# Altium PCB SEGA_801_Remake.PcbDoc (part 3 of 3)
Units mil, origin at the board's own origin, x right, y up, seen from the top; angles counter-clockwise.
Board outline 5905.51 x 7590.41 mil, 2 copper layers (Top Layer, Bottom Layer), stack 61.811 mil thick; 192 components, 203 nets, 858 pads, 614 vias.
Unrouted connection lines stored in the file: 107.
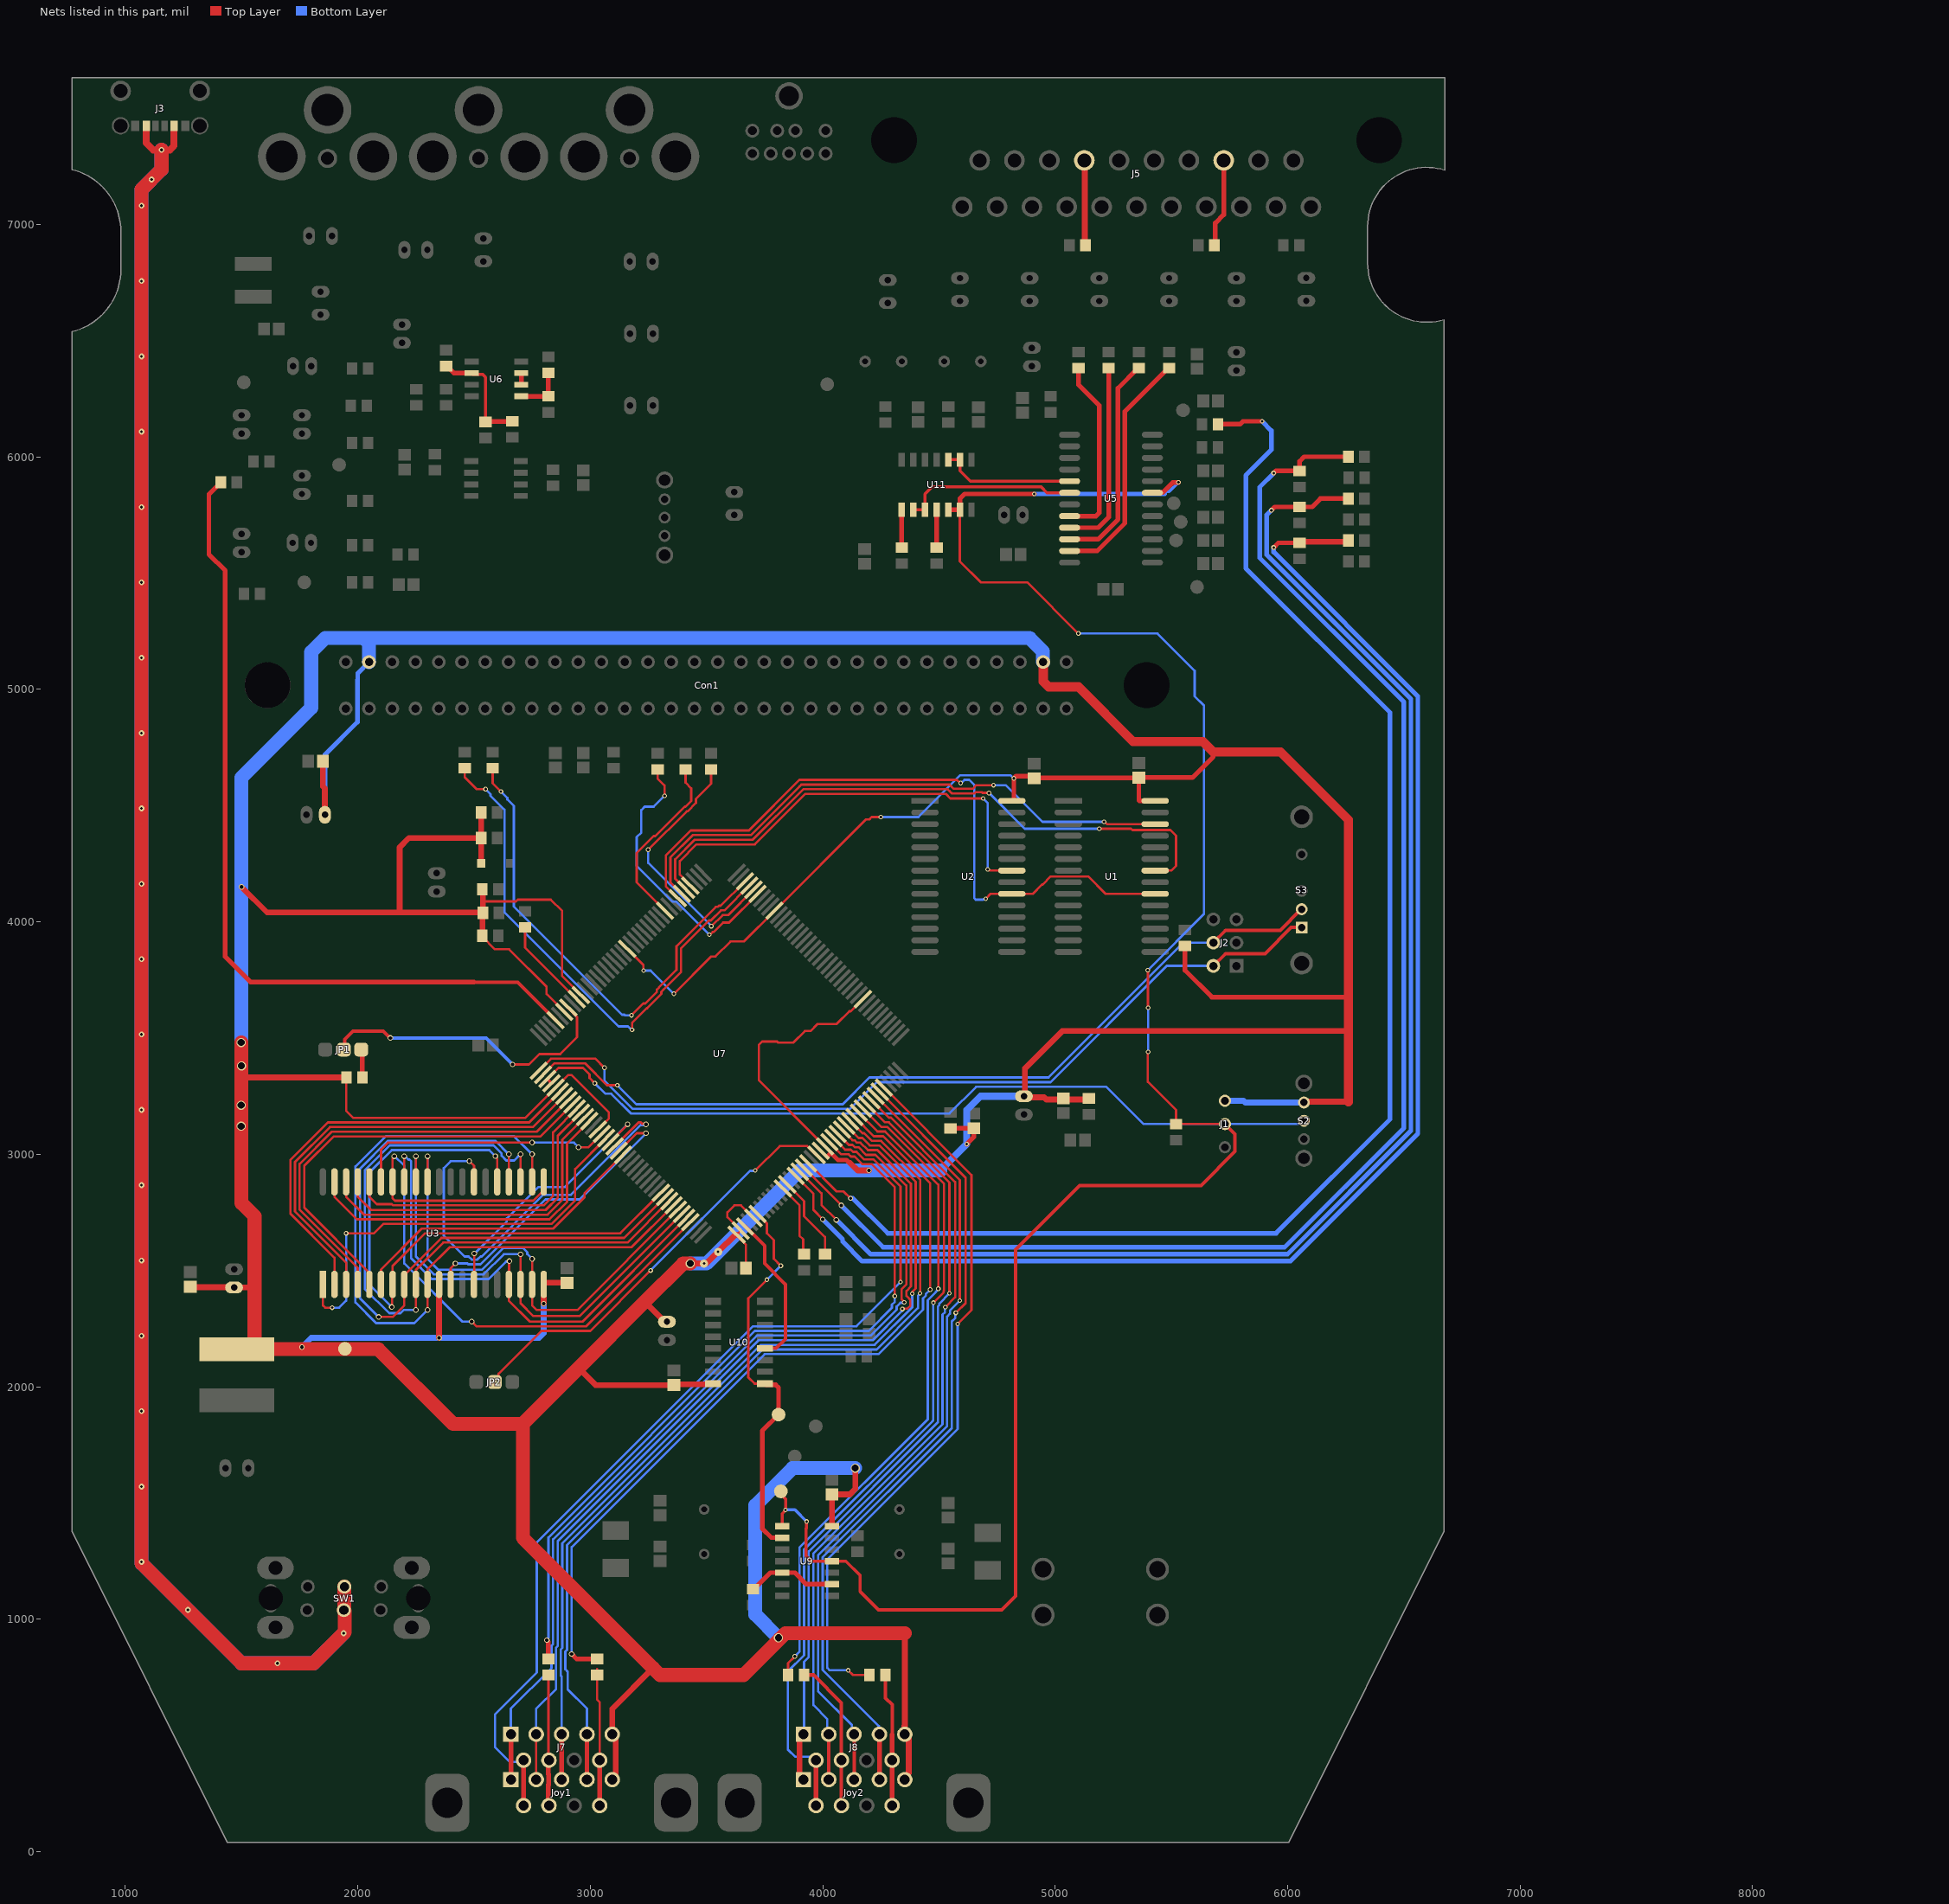
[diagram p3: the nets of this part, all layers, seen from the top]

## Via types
v1: diameter 25, hole 12, Top Layer to Bottom Layer, tented both sides, 269 vias
v2: diameter 19.68, hole 11.81, Top Layer to Bottom Layer, tented both sides, 183 vias
v3: diameter 31.5, hole 11.81, Top Layer to Bottom Layer, tented both sides, 82 vias
v4: diameter 23.62, hole 15.75, Top Layer to Bottom Layer, tented both sides, 36 vias
v5: diameter 35.43, hole 11.81, Top Layer to Bottom Layer, tented both sides, 35 vias
v6: diameter 39, hole 30, Top Layer to Bottom Layer, tented both sides, 7 vias
v7: diameter 19.68, hole 11.81, Top Layer to Bottom Layer, 2 vias

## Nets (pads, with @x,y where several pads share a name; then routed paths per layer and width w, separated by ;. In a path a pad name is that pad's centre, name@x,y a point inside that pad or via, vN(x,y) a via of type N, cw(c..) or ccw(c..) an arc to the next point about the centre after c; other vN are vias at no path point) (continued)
NetJ1_2: J1.2 R53.1 S2.2 TP4.1 U5.7 U7.3 U7.4 U9.1 U9.11 U11.5 U11.6 | length 12697.9
  Top Layer w10: U7.3@2815.27,3323.15 2815.67,3323.15 2863.53,3371.01 2969.25,3371.01 2997.41,3342.86 2997.41,3327.75 v2(3020,3305.16) ; U11.6@4590,5772.72 4590,5550 4680,5460 4880,5460 v2(5100,5240) ; v2(5398.29,3791.71) 5399.15,3790.85 5399.15,3630.85 v2(5400,3630) ; v2(5400,3440) 5398.29,3438.29 5398.29,3311.71 5520,3190 R53.1@5520,3128.9 5521.1,3130 J1.2@5730,3130
  Top Layer w13: U7.3@2815.27,3323.15 U7.4@2833.37,3305.05 ; TP4.1@3820,1550 3820,1537.54 3840,1517.54 v2(3840,1470) 3840,1468.19 3825.43,1453.62 U9.1@3825.43,1400 ; v2(3930.79,1420) 3929.51,1418.72 3929.51,1390.97 3927.44,1388.9 3927.44,1272.56 3950,1250 U9.11@4040,1250 4100,1250 4160,1190 4160,1120 4240,1040
  Top Layer w15: 4240,1040 4770,1040 4830,1100 4830,2589.8 5105.41,2865.22 5627.07,2865.22 5773.74,3011.88 5773.74,3086.26 J1.2@5730,3130
  Top Layer w20: U11.5@4540,5772.72 U11.6@4590,5772.72 4590,5820 4610,5840 v2(4910,5840) ; U5.7@5418.15,5845 5419.22,5846.07 5462.28,5846.07 5506.21,5890 v2(5530,5890)
  Bottom Layer w10: v2(3020,3305.16) 3065.16,3260 3090,3260 3174.79,3175.21 3181.64,3175.21 3181.69,3175.16 4545.16,3175.16 4659.96,3289.96 5220.04,3289.96 5380,3130 J1.2@5730,3130 6046.43,3130 6060.21,3143.78 S2.2@6070,3143.78 ; v2(5100,5240) 5440,5240 5600,5080 5600,4970 5640,4930 5640,4033.42 v2(5398.29,3791.71) ; v2(5400,3440) v2(5400,3630)
  Bottom Layer w13: v2(3840,1470) 3880.79,1470 v2(3930.79,1420) ; 5470,5840 5480,5850 5490,5850 v2(5530,5890)
  Bottom Layer w20: v2(4910,5840) 5470,5840
NetJ2_2: J2.2 S3.1 U7.1 | length 3747
  Top Layer w10: U7.1@2779.07,3359.35 2830.73,3411.01 3022.32,3411.01 v2(3061.11,3372.22)
  Top Layer w15: J2.2@5680,3810 5732.97,3862.97 5902.97,3862.97 6015.04,3975.04 S3.1@6060,3975.04
  Bottom Layer w10: v2(3061.11,3372.22) 3061.11,3317.17 3183.13,3195.16 4117.5,3195.16 4232.31,3309.96 4979.96,3309.96 5480,3810 J2.2@5680,3810
NetJ2_4: J2.4 S3.2 U7.2 | length 3703.6
  Top Layer w10: U7.2@2797.17,3341.25 2846.93,3391.01 2977.54,3391.01 3071.84,3296.71 v2(3116.71,3296.71)
  Top Layer w15: J2.4@5680,3910 5732.97,3962.97 5967.62,3962.97 6058.42,4053.78 S3.2@6060,4053.78
  Bottom Layer w10: v2(3116.71,3296.71) 3198.26,3215.16 4086.38,3215.16 4201.18,3329.96 4971.68,3329.96 5551.72,3910 J2.4@5680,3910
NetJ3_A9: J3.A9 J3.B9 SW1.3 SW1.4 | length 14937.1
  Top Layer w30: J3.A9@1090.16,7423.66 1090.16,7349.84 1120,7320 v7(1156.13,7320) 1192.27,7320 1209.84,7337.57 J3.B9@1209.84,7421.02
  Top Layer w60: v7(1156.13,7320) 1156.13,7235.98 1070,7149.84 1070,1240 1500,810 1810,810 1944.08,944.08 1944.08,1035.23 SW1.3@1940.25,1039.06 1942.46,1041.27 SW1.4@1942.46,1140
  Bottom Layer w60: v7(1156.13,7320) 1156.13,7236.13 1070,7150 1070,1240 1500,810 1810,810 v1@1940.73,940.73
  other v1: 1655,810 1939.72,939.72 1270,1040 1070,1246.48 1070,1570.57 1070,1894.65 1070,2218.73 1070,2542.82 1070,2866.9 1070,3190.99 1070,3515.07 1070,3839.16 1070,4163.24 1070,4487.32 1070,4811.41 1070,5135.49 1070,5459.58 1070,5783.66 1070,6107.75 1070,6431.83 1070,6755.92 1070,7080 1113.07,7193.07 1156.13,7320
NetJ5_8: J5.8 R72.2 | length 366.9
  Top Layer w25: J5.8@5125,7274.8 5127.5,7272.3 5127.5,6912.5 R72.2@5130,6910
NetJ5_16: J5.16 R71.2 | length 379.8
  Top Layer w20: R71.2@5688.9,6910 5688.9,7005.18 5725,7041.29 J5.16@5725,7274.8
NetJ7_1: J7.1 Joy1.1 U7.65 | length 3930.9
  Top Layer w10: U7.65@4064.31,3087.82 4112.37,3039.76 4128.53,3039.76 4138.28,3030 4153.81,3030 4186.31,2997.5 4227.04,2997.5 4359.69,2864.86 4359.69,2439.71 4340,2420.02 4340,2376.09 4350.38,2365.71 v2(4350.38,2363.09)
  Top Layer w20: Joy1.1@2658.78,330 J7.1@2658.78,504.92
  Bottom Layer w10: J7.1@2658.78,504.92 2658.78,614.96 2833.19,789.37 2833.19,886.28 2840,893.09 2840,1343.14 3716.86,2220 4206.57,2220 4317.87,2331.3 4317.87,2344.7 4334.4,2361.23 4348.53,2361.23 v2(4350.38,2363.09)
NetJ7_2: J7.2 Joy1.2 U7.66 | length 3917.5
  Top Layer w10: Joy1.2@2767.83,330 J7.2@2767.83,504.92 ; U7.66@4082.41,3105.93 4128.57,3059.76 4136.81,3059.76 4146.57,3050 4162.09,3050 4194.59,3017.5 4235.32,3017.5 4379.69,2873.14 4379.69,2431.43 4360,2411.74 4360,2389.97 4376.98,2373 4376.98,2348.43 4364.81,2336.26 4344.56,2336.26 v2(4342.71,2334.41)
  Bottom Layer w10: J7.2@2767.83,504.92 2767.83,614.96 2853.19,700.32 2853.19,877.67 2860,884.48 2860,1334.85 3725.15,2200 4215.15,2200 4340.86,2325.71 4340.86,2332.56 v2(4342.71,2334.41)
NetJ7_3: J7.3 Joy1.3 U7.67 | length 3872
  Top Layer w10: U7.67@4100.51,3124.03 4100.82,3124.03 4154.85,3070 4170.37,3070 4202.87,3037.5 4243.61,3037.5 4399.69,2881.42 4399.69,2423.14 4386.7,2410.15 4386.7,2402.12 v2(4384.84,2400.26)
  Top Layer w20: Joy1.3@2876.89,330 J7.3@2876.89,504.92
  Bottom Layer w10: J7.3@2876.89,504.92 2876.89,753.38 2873.19,757.08 2873.19,869.39 2880,876.2 2880,1326.57 3733.43,2180 4223.43,2180 4384.84,2341.41 v2(4384.84,2400.26)
NetJ7_4: J7.4 Joy1.4 U7.68 | length 3923.1
  Top Layer w10: U7.68@4118.61,3142.13 4170.74,3090 4178.66,3090 4211.16,3057.5 4251.89,3057.5 4419.69,2889.71 4419.69,2403.1 v2(4418.29,2401.71)
  Top Layer w20: Joy1.4@2985.94,330 J7.4@2985.94,504.92
  Bottom Layer w10: J7.4@2985.94,504.92 2985.94,614.96 2903.19,697.72 2903.19,774.41 2893.19,784.41 2893.19,861.11 2900,867.92 2900,1318.28 3741.72,2160 4231.72,2160 4409.69,2337.97 4409.69,2390.48 4418.29,2399.09 v2(4418.29,2401.71)
NetJ7_6: J7.6 Joy1.6 U7.64 | length 4097.7
  Top Layer w10: U7.64@4046.2,3069.72 4096.17,3019.76 4120.24,3019.76 4130,3010 4145.52,3010 4178.02,2977.5 4218.76,2977.5 4334.84,2861.41 v2(4334.84,2450)
  Top Layer w20: Joy1.6@2713.31,218.19 J7.6@2713.31,393.11
  Bottom Layer w10: J7.6@2713.31,393.11 2705.75,385.55 2654.45,385.55 2590,450 2590,590 2770,770 2770,1330 3700,2260 4144.84,2260 v2(4334.84,2450)
NetJ7_7: J7.7 Joy1.7 R78.1 | length 565.6
  Top Layer w10: R78.1@2820.25,759.75 2820.25,395.72 J7.7@2822.61,393.36
  Top Layer w20: Joy1.7@2822.36,198.11 2820,200.47 2820,286.75 2821.1,287.86 2821.1,331.99 2820,333.09 2820,390.75 J7.7@2822.61,393.36
NetJ7_9: J7.9 Joy1.9 R77.1 | length 565
  Top Layer w10: 3030,785.24 R77.1@3030,760 3030,653.67 3040.47,643.2 J7.9@3040.47,399.53
  Top Layer w20: Joy1.9@3040.47,218.19 J7.9@3040.47,393.11
NetJ8_1: J8.1 Joy2.1 U7.72 | length 3334.9
  Top Layer w10: U7.72@4191.02,3214.54 4268.06,3137.5 4285.03,3137.5 4545.16,2877.37 v2(4545.16,2401.71)
  Top Layer w25: J8.1@3915.47,504.92 3900,489.45 3900,326.81 Joy2.1@3916.89,309.92
  Bottom Layer w10: J8.1@3916.89,504.92 3920,508.03 3920,816.58 3940,836.58 3940,1291.24 4495.29,1846.53 4495.29,2345.02 4501.4,2351.13 4501.4,2357.95 v2(4545.16,2401.71)
NetJ8_2: J8.2 Joy2.2 U7.73 | length 3337.4
  Top Layer w10: U7.73@4209.12,3232.64 4284.26,3157.5 4293.31,3157.5 4570,2880.81 4570,2384.97 v2(4527.51,2342.48)
  Top Layer w15: Joy2.2@4025.94,330 J8.2@4025.95,504.92
  Bottom Layer w10: J8.2@4025.95,504.92 4020,510.87 4020,570 3960,630 3960,1282.95 4515.29,1838.24 4515.29,2310.14 4525.65,2320.51 4525.65,2340.62 v2(4527.51,2342.48)
NetJ8_3: J8.3 Joy2.3 U7.74 | length 3388.7
  Top Layer w10: U7.74@4227.22,3250.74 4300.46,3177.5 4301.6,3177.5 4590,2889.1 v2(4590,2370)
  Top Layer w15: Joy2.3@4135,330 J8.3@4135,504.92
  Bottom Layer w10: J8.3@4135,504.92 4125.91,514.01 4125.91,544.09 3980,690 3980,1274.67 4535.29,1829.96 4535.29,2301.86 4547.59,2314.16 4547.59,2327.43 4547.59,2327.86 4589.74,2370 v2(4590,2370)
NetJ8_4: J8.4 Joy2.4 U7.75 | length 3447.8
  Top Layer w10: U7.75@4245.32,3268.84 4614.84,2899.33 4614.84,2359.71 4572.7,2317.57 v2(4572.43,2317.57)
  Top Layer w20: Joy2.4@4244.06,330 J8.4@4244.06,504.92
  Bottom Layer w10: J8.4@4244.06,504.92 4241.79,507.18 4241.79,539.92 4000,781.72 4000,1266.39 4555.29,1821.68 4555.29,2280.16 4570.58,2295.45 4570.58,2315.71 v2(4572.43,2317.57)
NetJ8_6: J8.6 Joy2.6 U7.71 | length 3489.6
  Top Layer w10: U7.71@4172.92,3196.44 4251.85,3117.5 4276.75,3117.5 4522.04,2872.2 4522.04,2413.73 4520.32,2412 4520.32,2405.18 v2(4476.56,2361.42)
  Top Layer w20: Joy2.6@3971.42,218.19 J8.6@3971.42,393.11
  Bottom Layer w10: J8.6@3954.18,407.82 3950.29,403.93 3945.3,403.93 3941.41,407.82 3882.18,407.82 3850,440 3850,774.87 3920,844.87 3920,1299.52 4471.71,1851.24 4475.29,1854.81 4475.29,2360.16 v2(4476.56,2361.42)
NetJ8_7: J8.7 Joy2.7 R80.1 | length 651.7
  Top Layer w15: R80.1@3920,760 R80.1@3930,760 ; R80.1@3930,780 R80.1@3930,760 ; Joy2.7@4080.47,218.19 4080.47,503.15 4080.47,639.53 3960,760 R80.1@3930,760
NetJ8_9: J8.9 Joy2.9 R79.1 | length 553.7
  Top Layer w15: R79.1@4270,760 4270,660.81 4298.58,632.23 4298.58,503.15
  Top Layer w20: Joy2.9@4298.58,218.19 4298.58,503.15
NetJP1_1: JP1.1 R43.1 | length 122.1
  Top Layer w20: JP1.1@2015,3450 2020,3445 R43.1@2020,3330
NetJP1_2: JP1.2 U7.153 | length 1311.2
  Top Layer w10: v4(2666.04,3386.04) 2736.04,3386.04 2781.01,3431.01 2871.01,3431.01 2943.34,3503.34 2943.34,3576.51 2943.34,3589.79 2905.78,3627.34 U7.153@2905.78,3630.88
  Top Layer w15: JP1.2@1940,3450 1943.24,3453.24 1943.24,3493.24 1980,3530 2110,3530 v4(2140,3500)
  Bottom Layer w15: v4(2140,3500) 2552.08,3500 v4(2666.04,3386.04)
NetJP2_2: JP2.2 U7.60 | length 1831.4
  Top Layer w10: JP2.2@2590,2020 2605.81,2035.81 2605.81,2055.81 2790,2240 3000,2240 v2(3260,2500) ; v2(3710,2930) 3814.87,3034.87 3932.71,3034.87 3970.26,2997.32 U7.60@3973.8,2997.32
  Bottom Layer w10: v2(3260,2500) 3688.15,2928.15 3708.15,2928.15 v2(3710,2930)
NetR3_2: R3.2 R92.2 U7.55 | length 6214.6
  Top Layer w10: U7.55@3883.29,2906.81 3960,2830.09 3960,2760 v4(4000,2720)
  Top Layer w20: v2(5940,5610) 5960,5630 R3.2@6051.1,5630 R3.2@6056.1,5635
  Top Layer w25: R3.2@6056.1,5635 6256.1,5635 R92.2@6261.1,5640
  Bottom Layer w20: v4(4000,2720) 4085.35,2634.65 4085.35,2624.65 4170,2540 6011.42,2540 6560,3088.58 6560,4970 5940,5590 v2(5940,5610)
NetR4_2: R4.2 R91.2 U7.56 | length 6310.5
  Top Layer w10: U7.56@3901.39,2924.91 3994.72,2831.57 3994.72,2782.01 v4(4058.85,2717.89)
  Top Layer w20: v2(5930,5770) 5944.45,5784.45 6105.55,5784.45 6141.1,5820 R91.2@6261.1,5820
  Bottom Layer w20: v4(4058.85,2717.89) 4206.73,2570 5998.99,2570 6530,3101.01 6530,4957.57 5910,5577.57 5910,5750 v2(5930,5770)
NetR5_2: R5.2 R90.2 U7.57 | length 6410
  Top Layer w10: U7.57@3919.49,2943.01 3919.49,2941.76 4080,2781.25 v4(4080,2780)
  Top Layer w20: v2(5940,5930) 5950,5940 6050,5940 R5.2@6051.1,5938.9 6051.1,5980 6071.1,6000 R90.2@6261.1,6000
  Bottom Layer w20: v4(4080,2780) 4260,2600 5986.57,2600 6500,3113.43 6500,4945.15 5880,5565.15 5880,5870 v2(5940,5930)
NetR15_2: R15.2 U7.58 | length 6346.7
  Top Layer w10: U7.58@3937.59,2961.11 3938.89,2961.11 4060,2840 4090,2840 v2(4120,2810)
  Top Layer w20: R15.2@5700,6140 5795.07,6140 5807.57,6152.5 v2(5890,6152.5)
  Bottom Layer w20: v2(4120,2810) 4130,2810 4280,2660 5950,2660 6440,3150 6440,4900 5820,5520 5820,5920 5930,6030 5930,6112.5 v2(5890,6152.5)
NetR21_2: R21.2 R22.2 U6.5 | length 217.6
  Top Layer w20: U6.5@2703.54,6260 R22.2@2820,6260 R21.2@2820,6361.1
NetR24_2: R24.2 R25.2 R28.1 U6.2 | length 498.4
  Top Layer w13: U6.2@2490,6360 2496.3,6353.7 2538.68,6353.7 2550,6342.38 R24.2@2550,6150
  Top Layer w20: R28.1@2380,6390 2383.94,6390 2413.94,6360 U6.2@2490,6360 ; R24.2@2550,6150 2551.51,6151.51 2663.52,6151.51 R25.2@2665.04,6153.03
NetR31_1: R31.1 U5.23 | length 1035.2
  Top Layer w20: U5.23@5061.85,5595 5180.46,5595 5300,5714.54 5300,6195.04 5486.06,6381.1 R31.1@5490,6381.1
NetR32_1: R32.1 U5.21 | length 827.9
  Top Layer w20: U5.21@5061.85,5695 5185,5695 5230,5740 R32.1@5230,6381.1
NetR33_1: R33.1 U5.20 | length 793
  Top Layer w20: U5.20@5061.85,5745 5175.36,5745 5190,5759.64 5190,6220 5100,6310 R33.1@5100,6381.1
NetR35_1: R35.1 U5.22 | length 933.8
  Top Layer w20: U5.22@5061.85,5645 5184.5,5645 5270,5730.5 5270,6295.04 5356.06,6381.1 R35.1@5360,6381.1
NetR36_2: R36.2 U11.1 | length 166.9
  Top Layer w13: R36.2@4340,5608.9 R36.2@4350,5618.9
  Top Layer w20: R36.2@4340,5620 U11.1@4340,5772.72
NetR40_1: R40.1 U7.151 | length 400.4
  Top Layer w10: R40.1@2720,3975.55 2720,3889.07 U7.151@2941.99,3667.08
NetR51_1: R51.1 U7.130 | length 772.9
  Top Layer w10: U7.130@3322.13,4047.22 3199.68,4169.67 3199.68,4295.45 3272.53,4368.29 3279.83,4368.29 3406.69,4495.16 3410.29,4495.16 3434.52,4519.38 3434.52,4573.95 3410,4598.46 R51.1@3410,4655.55
NetR57_1: R57.1 U7.118 | length 2125.5
  Top Layer w10: R57.1@2580,4660 2580,4595.91 2615.59,4560.33 v2(2616.24,4560.33) ; v2(3177.38,3597.65) 3227.83,3648.09 3236.64,3648.09 3286.05,3697.51 3286.05,3706.97 3295.16,3716.08 3295.16,3716.86 3371.02,3792.72 3371.02,3894.42 3540.64,4064.05 3548.41,4064.05 3553.15,4068.79 3560.92,4068.79 U7.118@3666.06,4173.94
  Bottom Layer w10: v2(2616.24,4560.33) 2643.9,4532.67 2643.9,4525.82 2671.36,4498.36 2671.36,4065.51 3136.86,3600 3147.54,3600 3149.89,3597.65 v2(3177.38,3597.65)
NetR58_1: R58.1 U7.117 | length 2315.4
  Top Layer w10: R58.1@2460,4660 2460,4622.36 2512.36,4570 v2(2550,4570) ; v2(3180,3534.84) 3180,3565.13 3242.96,3628.09 3244.93,3628.09 3306.05,3689.22 3306.05,3698.69 3315.16,3707.79 3315.16,3708.57 3391.02,3784.44 3391.02,3886.14 3510.74,4005.86 3518.99,4005.86 3561.92,4048.79 3577.12,4048.79 U7.117@3684.16,4155.84
  Bottom Layer w10: v2(2550,4570) 2571.07,4548.93 2571.07,4542.08 2631.36,4481.79 2631.36,4040.36 3121.72,3550 3130.29,3550 3162.22,3550 3177.38,3534.84 v2(3180,3534.84)
NetR59_1: R59.1 U7.116 | length 1152.1
  Top Layer w10: v2(3249.37,4310) 3249.82,4310 3414.98,4475.16 3418.57,4475.16 3454.52,4511.1 3454.52,4527.93 3520,4593.42 R59.1@3520,4660 ; v2(3521.03,3981.02) 3522.43,3981.02 3570.21,4028.79 3593.32,4028.79 U7.116@3702.27,4137.73
  Bottom Layer w10: v2(3249.37,4310) 3249.37,4252.68 v2(3521.03,3981.02)
NetR60_1: R60.1 U7.115 | length 1231.2
  Top Layer w10: R60.1@3290,4671.1 3290,4616.57 3319.68,4586.88 v2(3319.68,4541.83) ; v2(3512.44,3944.62) 3515.06,3944.62 3526.62,3956.18 3531.32,3956.18 3571.44,3996.29 3597.03,3996.29 U7.115@3720.37,4119.63
  Bottom Layer w10: v2(3319.68,4541.83) 3273.01,4495.16 3234.38,4495.16 3219.68,4480.47 3219.68,4384.07 3199.68,4364.07 3199.68,4240.11 3353.74,4086.05 3370.24,4086.05 3511.67,3944.62 v2(3512.44,3944.62)
NetR77_2: R77.2 U7.69 | length 3509.7
  Top Layer w10: U7.69@4136.71,3160.23 4219.44,3077.5 4260.18,3077.5 4462.43,2875.24 v2(4462.43,2417.57)
  Top Layer w20: v4(2920,850) 2920.98,850 2942.08,828.9 R77.2@3026.06,828.9
  Bottom Layer w10: v4(2920,850) 2920,1310 3750,2140 4240,2140 4431.71,2331.71 4431.71,2380 4443.13,2391.42 4443.13,2398.27 v2(4462.43,2417.57)
NetR78_2: R78.2 U7.63 | length 3300.9
  Top Layer w10: U7.63@4028.1,3051.62 4079.96,2999.76 4111.96,2999.76 4121.72,2990 4137.24,2990 4169.74,2957.5 4210.47,2957.5 4310,2857.97 v2(4310,2390)
  Top Layer w20: v4(2813.19,910) 2813.19,909.02 2820,902.21 R78.2@2820,828.9
  Bottom Layer w10: v4(2813.19,910) 2813.19,913.69 2820,920.5 2820,1351.42 3708.58,2240 4198.28,2240 4297.87,2339.58 4297.87,2352.99 4310,2365.12 v2(4310,2390)
NetR79_2: R79.2 U7.76 | length 3103.3
  Top Layer w10: v2(4110,780) 4130,760 R79.2@4201.1,760 ; U7.76@4263.43,3286.94 4640,2910.37 4640,2329.74 v2(4580.13,2269.87)
  Bottom Layer w10: v2(4110,780) 4030,780 4020,790 4020,1258.1 4580.13,1818.23 v2(4580.13,2269.87)
NetR80_2: R80.2 U7.70 | length 2847
  Top Layer w10: R80.2@3851.1,760 3851.1,811.1 v2(3880,840) ; U7.70@4154.81,3178.33 4235.65,3097.5 4268.46,3097.5 4497.2,2868.76 v2(4497.2,2421.1)
  Bottom Layer w10: v2(3880,840) 3900,860 3900,1307.81 4451.71,1859.52 4451.71,2371.71 4487.28,2407.28 4487.28,2408.56 4497.2,2418.48 v2(4497.2,2421.1)
NetR93_2: R93.2 U9.5 U9.9 | length 390.2
  Top Layer w20: R93.2@3700,1128.9 3703.94,1128.9 3775.04,1200 U9.5@3825.43,1200 3880,1200 3930,1150 U9.9@4040,1150
NetR96_2: R96.2 U11.4 | length 162.7
  Top Layer w20: R96.2@4490,5610 U11.4@4490,5772.72
NetR97_1: R97.1 U7.52 | length 318.6
  Top Layer w10: U7.52@3828.98,2852.5 3828.98,2852 3900,2780.98 3900,2650 3915.86,2634.14 3915.86,2587.64 3924.6,2578.9 R97.1@3930,2578.9
NetR98_1: R98.1 U7.53 | length 368.1
  Top Layer w10: U7.53@3847.08,2870.6 3920,2797.68 3920,2733.8 4010,2643.8 R98.1@4010,2570
NetR99_1: R99.1 U7.156 | length 3624.9
  Top Layer w15: 2500,3740 2688.05,3740 U7.156@2851.48,3576.57
  Top Layer w20: R99.1@1411.1,5890 1360,5838.9 1360,5580 1430,5510 1430,3850 1540,3740 2500,3740
NetTP3_1: TP3.1 U7.46 U9.2 U10.1 | length 1688.2
  Top Layer w10: U7.46@3720.37,2743.89 3720.37,2742 3760,2702.37 3760,2660 3790,2630 3790,2550 v2(3820,2520) ; U10.1@3751.22,2013.03 3706.97,2013.03 3680,2040 3680,2380 v2(3760,2460)
  Top Layer w20: U10.1@3751.22,2013.03 3756.07,2008.18 3797.57,2008.18 3810,1995.76 TP3.1@3810,1880 3740,1810 3740,1390 3779.36,1350.64 3824.79,1350.64 U9.2@3825.43,1350
  Bottom Layer w10: v2(3760,2460) v2(3820,2520)
NetU1_20: U1.20 U2.20 U7.127 | length 2975.9
  Top Layer w10: U7.127@3376.43,4101.53 3325.16,4152.8 3325.16,4285.14 3432.61,4392.59 3682.61,4392.59 3900.01,4610 4577.38,4610 4590.88,4596.5 v2(4593.5,4596.5) ; v2(4700.99,4099.01) 4721.98,4120 4903.5,4120 4943.5,4160 4946.57,4160 4981.17,4194.6 5141.55,4194.6 5216.14,4120 U1.20@5380,4120
  Bottom Layer w10: v2(4593.5,4596.5) 4596.12,4596.5 4609.63,4610 4630,4610 4652.27,4587.73 4652.27,4101.02 4658.13,4095.16 4690.29,4095.16 4692.29,4097.16 4699.14,4097.16 v2(4700.99,4099.01)
NetU1_22: U1.22 U7.125 | length 2746.4
  Top Layer w10: U7.125@3412.64,4137.73 3365.16,4185.21 3365.16,4268.57 3449.17,4352.59 3699.17,4352.59 3909.18,4562.6 3916.58,4570 4537.5,4570 4544.9,4562.6 4555.85,4551.66 4653.1,4551.66 4659.2,4557.76 4683.98,4557.76 4686.89,4554.84 4714.28,4554.84 v2(4715.31,4553.81) ; v2(5190,4400) 5326.31,4400 5331.71,4394.6 5495.4,4394.6 5520,4370 5520,4240 5500,4220 U1.22@5430,4220
  Bottom Layer w10: v2(4715.31,4553.81) 4869.12,4400 v2(5190,4400)
NetU1_26: U1.26 U7.126 | length 2425.7
  Top Layer w10: U7.126@3394.54,4119.63 3345.16,4169.01 3345.16,4276.86 3440.89,4372.59 3690.89,4372.59 3900.9,4582.6 3908.3,4590 4545.79,4590 4553.19,4582.6 4564.13,4571.66 4644.82,4571.66 4660.6,4587.44 v2(4735.16,4587.44) ; v2(5210,4430) 5212.62,4430 5222.62,4420 U1.26@5380,4420
  Bottom Layer w10: v2(4735.16,4587.44) 4787.43,4587.44 4944.87,4430 v2(5210,4430)
NetU2_22: U2.22 U7.124 | length 1975.3
  Top Layer w10: U7.124@3430.74,4155.84 3430.74,4156.6 3385.16,4202.18 3385.16,4260.29 3457.46,4332.59 3707.46,4332.59 3924.87,4550 4529.22,4550 4549.22,4530 v2(4690,4530) ; v2(4710,4225.16) 4712.62,4225.16 4717.78,4220 U2.22@4813.62,4220
  Bottom Layer w10: v2(4690,4530) 4710,4510 v2(4710,4225.16)
NetU3_1: U3.1 U7.17 | length 1863.6
  Top Layer w10: U3.1@1850,2440 1850,2350 1860,2340 v2(1890,2340) ; v2(1950,2660) 2070,2660 2110,2700 2833.14,2700 2935.01,2801.87 2935.01,2936.03 U7.17@3068.7,3069.72
  Bottom Layer w10: v2(1890,2340) 1920,2340 1950,2370 v2(1950,2660)
NetU3_2: U3.2 U7.6 | length 1894.9
  Top Layer w10: U3.2@1900,2440 1900,2555.15 1710,2745.15 1710,2974.85 1871.96,3136.81 2737.55,3136.81 U7.6@2869.58,3268.84
NetU3_3: U3.3 U7.7 | length 1893.1
  Top Layer w10: U3.3@1950,2440 1950,2533.43 1730,2753.43 1730,2966.57 1880.24,3116.81 2753.75,3116.81 U7.7@2887.68,3250.74
NetU3_4: U3.4 U7.8 | length 1891.3
  Top Layer w10: U3.4@2000,2440 2000,2511.72 1750,2761.72 1750,2958.28 1888.53,3096.81 2769.95,3096.81 U7.8@2905.78,3232.64
NetU3_5: U3.5 U7.9 | length 1889.4
  Top Layer w10: U3.5@2050,2440 2046.93,2443.07 2046.93,2493.07 1770,2770 1770,2950 1896.81,3076.81 2786.16,3076.81 U7.9@2923.88,3214.54
NetU3_6: U3.6 U7.21 | length 1319.9
  Top Layer w10: U3.6@2100,2440 2100,2504.21 2275.79,2680 2841.42,2680 2975.35,2813.93 2975.35,2831.56 U7.21@3141.11,2997.32
NetU3_7: U3.7 U3.25 U7.30 | length 2788.8
  Top Layer w10: v4(2146.43,2342.81) 2148.22,2344.59 2148.22,2438.22 U3.7@2150,2440 2150,2520 2290,2660 3129.63,2660 U7.30@3304.03,2834.4 ; v4(2591.9,2991.9) 2591.9,2988.21 2600,2980.11 U3.25@2600,2880.94
  Bottom Layer w10: v4(2146.43,2342.81) 2050,2439.24 2050,2921.86 2146.14,3018 2565.8,3018 v4(2591.9,2991.9)
NetU3_8: U3.8 U3.24 U7.31 | length 3026.3
  Top Layer w10: v4(2090,2300) 2150,2300 2200,2350 2200,2480 2360,2640 3145.83,2640 U7.31@3322.13,2816.3 ; U3.24@2650,2880.94 v4(2650,3000)
  Bottom Layer w10: v4(2090,2300) 2010,2380 2010,2938.43 2129.57,3058 2592,3058 v4(2650,3000)
NetU3_9: U3.9 U3.23 U7.32 | length 3040.3
  Top Layer w10: v4(2250,2330) 2250,2501.72 2368.28,2620 3160,2620 3338.19,2798.19 U7.32@3340.23,2798.19 ; U3.23@2700,2880.94 v4(2700,3000)
  Bottom Layer w10: v4(2250,2330) 2197.82,2330 2183.82,2316 2135.33,2316 2030,2421.33 2030,2930.15 2137.85,3038 2583.72,3038 2618.71,3003.01 2618.71,2993.37 2638.89,2973.19 2673.19,2973.19 v4(2700,3000)
NetU3_10: U3.10 U3.22 U7.33 | length 3267.5
  Top Layer w10: v4(2300,2330) 2300,2504.21 2395.79,2600 3178.24,2600 U7.33@3358.33,2780.09 ; U3.22@2750,2880.94 v4(2750,3000)
  Bottom Layer w10: v4(2300,2330) 2243.19,2273.19 2078.89,2273.19 1990,2362.08 1990,2946.72 2121.28,3078 2672,3078 v4(2750,3000)
NetU3_12: U3.12 U7.20 | length 1301.1
  Top Layer w10: U3.12@2400,2440 2400,2510 v4(2420,2530) ; U7.20@3123.01,3015.42 3125.42,3015.42 3200,3090 v4(3240,3090)
  Bottom Layer w10: v4(2420,2530) 2471.32,2530 2474.94,2526.38 2528.09,2526.38 2807.01,2805.29 2955.29,2805.29 v4(3240,3090)
NetU3_14: U3.14 U7.18 | length 1138.4
  Top Layer w10: U3.14@2500,2440 2500.8,2440.8 2500.8,2572.39 v4(2501.59,2573.19) ; U7.18@3086.8,3051.62 3086.8,3053.41 3160.65,3127.26 v4(3160.65,3129.05)
  Bottom Layer w10: v4(2501.59,2573.19) 2503.19,2573.19 2641.28,2711.28 2641.28,2723.71 2776.77,2859.2 2890.8,2859.2 v4(3160.65,3129.05)
NetU3_17: U3.17 U3.33 U7.36 | length 2213.8
  Top Layer w10: U3.33@2200,2880.94 v4(2200,2991.19) ; v4(2652.43,2540) 2651.21,2538.79 2651.21,2441.21 U3.17@2650,2440 2650,2370 2740,2280 2966.85,2280 U7.36@3412.64,2725.79
  Bottom Layer w10: v4(2200,2991.19) 2203.69,2991.19 2217.8,2977.07 2222.93,2977.07 2230,2970 2230,2580 2230,2551.72 2318.53,2463.19 2346.81,2463.19 2563.19,2463.19 2637.39,2537.39 2649.82,2537.39 v4(2652.43,2540)
NetU3_18: U3.18 U3.32 U7.35 | length 2168.7
  Top Layer w10: U3.32@2250,2880.94 v4(2250,2991.19) ; v4(2700,2569.19) 2700,2360 2756,2304 2954.65,2304 U7.35@3394.54,2743.89
  Bottom Layer w10: v4(2250,2991.19) 2250,2560 2326.81,2483.19 2541.47,2483.19 2628.28,2570 2699.19,2570 v4(2700,2569.19)
NetU3_19: U3.19 U3.31 U7.34 | length 2097.3
  Top Layer w10: U3.31@2300,2880.94 v4(2300,2991.19) ; v4(2750,2550) U3.19@2750,2440 2750,2350.01 2770.01,2330 2944.44,2330 U7.34@3376.43,2761.99
  Bottom Layer w10: v4(2300,2991.19) 2300,2550 2346.81,2503.19 2533.19,2503.19 2626.81,2596.81 2711.11,2596.81 2729.25,2578.67 2729.25,2570.75 v4(2750,2550)
NetU3_21: U3.21 U3.34 U7.37 | length 2900.4
  Top Layer w10: v4(2157.24,2991.19) 2157.24,2987.5 2150,2980.26 U3.34@2150,2880.94 2150,2810 2160,2800 2754.49,2800 2800,2845.51 U3.21@2800,2880.94 ; v4(2490,2280) 2510,2260 2983.06,2260 U7.37@3430.74,2707.68
  Bottom Layer w10: v4(2157.24,2991.19) 2158.81,2991.19 2200,2950 2200,2530 2450,2280 v4(2490,2280)
NetU3_27: U3.27 U7.19 | length 1845.3
  Top Layer w10: v4(2480,2970) 2500,2950 U3.27@2500,2880.94 ; U7.19@3104.9,3033.52 3208.19,3136.8 3217.86,3136.8 3223.71,3130.95 3237.39,3130.95 v4(3240,3128.35)
  Bottom Layer w10: v4(2480,2970) 2400,2970 2370,2940 2370,2649.66 2459.66,2560 2476.87,2560 2490.49,2546.38 2514.29,2546.38 2527.92,2560 2533.43,2560 2798.72,2825.29 2916.94,2825.29 3217.39,3125.74 3237.39,3125.74 v4(3240,3128.35)
NetU3_35: U3.35 U7.16 | length 1134.3
  Top Layer w10: U3.35@2100,2880.94 2100,3020 2130,3050 v4(2750,3050) ; v4(2950,3030) 2992.77,3030 U7.16@3050.6,3087.82
  Bottom Layer w10: v4(2750,3050) 2930,3050 v4(2950,3030)
NetU3_36: U3.36 U7.10 | length 1304.7
  Top Layer w10: U3.36@2050,2880.94 2050,2816.73 2081.37,2785.37 2146.35,2785.37 2151.72,2780 2800,2780 2840,2820 2840,3094.45 U7.10@2941.99,3196.44
NetU3_37: U3.37 U7.11 | length 1377.2
  Top Layer w10: U3.37@2000,2880.94 2000,2816.73 2056.73,2760 2783.47,2760 2808.28,2760 2860,2811.72 2860,3078.25 U7.11@2960.09,3178.33
NetU3_38: U3.38 U7.12 | length 1449.7
  Top Layer w10: U3.38@1950,2880.94 1950,2816.73 2026.73,2740 2816.57,2740 2880,2803.43 2880,3062.04 U7.12@2978.19,3160.23
NetU3_39: U3.39 U7.13 | length 1522.3
  Top Layer w10: U3.39@1900,2880.94 1900,2816.73 1996.73,2720 2824.85,2720 2900,2795.15 2900,3045.84 U7.13@2996.29,3142.13
NetU5_17: U5.17 U11.9 U11.10 | length 587.8
  Top Layer w13: U11.10@4540,5987.28 U11.9@4590,5987.28 4590,5940 4635,5895 U5.17@5061.85,5895
NetU5_18: U5.18 U11.2 U11.3 | length 761.9
  Top Layer w13: U11.2@4390,5772.72 U11.3@4440,5772.72 4440,5840 4470,5870 4940,5870 4965,5845 U5.18@5061.85,5845
NetU6_6: U6.6 U6.7 | length 50
  Top Layer w20: U6.6@2703.54,6310 U6.7@2703.54,6360
NetU7_43: U7.43 U10.4 | length 661.8
  Top Layer w15: U7.43@3666.06,2689.58 3750,2605.64 3750,2530 3840,2440 3840,2205.23 3799.77,2165 U10.4@3751.22,2165
VCC: C1.1 C2.1 C3.1 C23.1 C37.1 C38.1 C42.1 C43.1 C45.1 C51.1 C52.1 C54.1 C56.1 C57.1 Con1.34 Con1.63 D1.2 J1.3 J7.5 J8.5 Joy1.5 Joy2.5 L1.2 R43.2 R52.2 R56.1 R63.2 R64.2 R65.2 R66.2 R68.2 R70.2 S2.3 TP10.1 U1.28 U2.28 U3.11 U3.20 U7.5 U7.15 U7.41 U7.42 U7.45 U7.61 U7.62 U7.90 U7.111 U7.139 U7.150 U7.154 U9.14 U10.16 | length 36750.6
  Top Layer w10: R43.2@1951.1,3330 1950,3328.9 1950,3186.81 1980,3156.81 2721.34,3156.81 U7.5@2851.48,3286.94 2904.53,3340 2920,3340 3080,3180 3080,3153.43 U7.15@3032.5,3105.93 ; R64.2@2535.55,3940 2535.55,3936.06 2590.04,3881.57 2650.93,3881.57 2812.5,3720 2812.5,3689.35 2887.68,3614.17 U7.154@2887.68,3612.78 ; R65.2@2535.55,4035.43 R65.2@2538.62,4038.5 ; R66.2@2535.55,4140 R66.2@2538.62,4136.93 ; 2538.62,4087.72 2680.89,4087.72 2688.02,4094.84 2830.29,4094.84 2879.28,4045.85 2879.28,3765.99 U7.150@2960.09,3685.19 ; U7.139@3159.21,3884.31 3228.68,3814.84 3228.68,3791.32 v2(3230,3790) ; v2(3360,3690) 3520.86,3850.86 3539.14,3850.86 3603.13,3914.84 3660.39,3914.84 U7.111@3792.78,4047.22 4185.55,4440 4200,4440 4210,4450 v2(4250,4450) ; C23.1@3670,2510 3670,2609.7 3629.86,2649.84 U7.41@3629.86,2653.38 U7.42@3647.96,2671.48 3590,2729.44 3590,2750 3620,2780 3648.05,2780 U7.45@3702.27,2725.79 ; U7.62@4010,3033.52 3725.16,3318.36 3725.16,3470.29 3739.71,3484.84 3804.02,3484.84 3808.86,3480 3873.17,3480 3923.17,3530 3947.72,3530 3977.72,3560 4060,3560 4114.84,3614.84 4120.67,3614.84 U7.90@4172.92,3667.08 ; R52.2@4550,3110.36 R52.2@4551.46,3111.81
  Top Layer w19.51: U7.61@4021.95,2992.44 U7.62@4034.92,3005.41 ; U7.62@4037.28,3003.89 4066.17,2975 4101.7,2975 4114.2,2962.5 4118.03,2962.5
  Top Layer w20: R52.2@4551.46,3111.81 C37.1@4650,3111.81 4650,3073.43 v2(4620,3043.43) ; U2.28@4813.62,4520 4819.8,4520 4822.2,4522.4 v2(4822.2,4617.01) 4831.49,4626.29 4900.71,4626.29 C3.1@4910,4617.01 4911.5,4618.5 5358.5,4618.5 C51.1@5360,4620 ; U1.28@5380,4520 5362.4,4520 5360,4522.4 C51.1@5360,4620 ; R63.2@5558.13,3881.35 5558.13,3791.15 5673.58,3675.7 6261.92,3675.7 ; 5680,4730 5680,4709.29 5590.71,4620 C51.1@5360,4620
  Top Layer w25: C57.1@1280,2430 1281.72,2428.28 1466.2,2428.28 C56.1@1467.91,2426.56 1552.86,2426.56 1556.3,2430 ; 1500,3320 1510,3330 R43.2@1951.1,3330 ; v4(1500,4150) 1610,4040 2180,4040 ; C2.1@1850,4690 1850,4581.78 1858.74,4573.04 C52.1@1858.74,4460 ; v4(2350,2210) U3.11@2350,2440 ; R68.2@2531.1,4470 R70.2@2531.1,4360 ; R66.2@2533.58,4141.97 R66.2@2535.55,4140 ; D1.2@2533.58,4248.66 D1.2@2531.61,4250.63 2531.36,4250.89 2531.36,4359.74 R70.2@2531.1,4360 ; R64.2@2535.55,3940 2537.09,3941.53 2537.09,4033.9 2535.55,4035.43 2533.05,4035.43 2528.48,4040 2180,4040 ; R65.2@2538.62,4038.5 2538.62,4087.72 R66.2@2538.62,4136.93 ; v4(2800,2357.5) U3.20@2800,2440 2800,2445.83 2801.18,2447.01 C1.1@2900,2447.01 ; 2950,2080 3022.99,2007.01 C54.1@3360,2007.01 3363.01,2010.02 3525.77,2010.02 U10.16@3528.78,2013.03 ; Joy1.5@3095,309.92 3095,321.16 3110,336.16 3110,513.68 3095,528.68 3095,614.96 3270,789.96 ; 3235,2365 3320.63,2279.37 C38.1@3330,2279.37 ; v6(3430,2530) v5(3490,2530) 3492,2532 3502,2532 v5(3550,2580) 3623.38,2653.38 U7.41@3629.86,2653.38 ; U9.14@4040,1400 C45.1@4040,1537.01 4117.01,1537.01 4140,1560 v6(4140,1650) ; 4118.03,2962.5 4150.53,2930 v4(4199.08,2930) ; 4351.69,539.92 4351.69,528.68 4370,510.37 4370,338.05 4353.11,321.16 Joy2.5@4353.11,309.92 ; 4353.11,539.92 4353.11,614.96 4353.11,940 ; R56.1@5149.7,3235.7 R56.1@5145.39,3240 5141.09,3235.7 5039.7,3235.7 C42.1@5035.39,3240 5031.09,3235.7 4961.91,3235.7 4952.54,3245.07 4869.7,3245.07 C43.1@4865.39,3249.37 4870,3253.98 4870,3370 5030,3530 6261.92,3530 ; 5780,4730 5785.7,4735.7 ; S2.3@6070,3222.52 6073.18,3225.7 6261.92,3225.7 ; 2180,4040 2180,4320 2220,4360 R70.2@2531.1,4360
  Top Layer w39: 5780,4730 5970,4730 6261.92,4438.08 6261.92,3675.7 6261.92,3530 6261.92,3225.7
  Top Layer w40: Con1.34@4948.42,5117.22 4948.42,5033.43 4971.86,5010 5100,5010 5335,4775 5635,4775 5680,4730 5780,4730
  Top Layer w60: L1.2@1480,2161.65 1545.12,2161.65 1944.82,2161.65 2088.35,2161.65 2410,1840 2710,1840 ; v6@1500,3480.45 v6(1500,3380) 1500,3320 1500,2790 1556.3,2733.7 1556.3,2430 L1.2@1556.3,2172.83 ; v6(3430,2530) 3400,2530 3235,2365 2950,2080 2710,1840 ; 4353.11,940 3840,940 3815,915 3660,760 3300,760 3270,790 2710,1350 2710,1840
  Top Layer w80: L1.2@1545.12,2161.65 L1.2@1556.3,2172.83
  Bottom Layer w10: v2(3230,3790) 3260,3790 v2(3360,3690) ; v2(4250,4450) 4411.87,4450 4591.87,4630 4806.59,4630 4819.58,4617.01 v2(4822.2,4617.01)
  Bottom Layer w20: C52.1@1858.74,4460 1860,4461.26 1860,4720 1998.9,4858.9 1998.9,5038.9 2000,5040 2000,5068.79 Con1.63@2048.42,5117.22
  Bottom Layer w25: v4(1760,2170) 1800,2210 v4(2350,2210) 2780,2210 2800,2230 v4(2800,2357.5) ; J1.3@5730,3230 5810,3230 5817.48,3222.52 S2.3@6070,3222.52
  Bottom Layer w30: 4506.57,2930 v2(4620,3043.43) 4620,3190 4679.37,3249.37 C43.1@4865.39,3249.37
  Bottom Layer w60: v6@1500,3110 v6(1500,3380) v4(1500,4150) 1500,4620 1800,4920 1800,5160 1860,5220 2025.58,5220 ; Con1.63@2048.42,5117.22 2048.42,5197.15 2025.58,5220 ; v6(3430,2530) v5@3480,2530 ; v5(3490,2530) 3500,2530 3900,2930 v4(4199.08,2930) 4506.57,2930 ; v6(3810,920) 3710,1020 3710,1490 3870,1650 v6(4140,1650) ; Con1.34@4948.42,5117.22 4947.36,5118.28 4947.36,5162.64 4890,5220 2025.58,5220
  other v6: 1498.52,3120.45 1498.52,3210.45 1498.52,3480.45
pads on no net: Con1.65 Con1.66 J2.6 J3.A5 J3.B5 J5.1 J5.3 J5.10 J5.12 J5.14 J5.19 J5.MH1 J5.MH2 JP1.3 S3.4 SW1.5 SW1.6 U3.13 U3.15 U3.26 U3.28 U5.5 U5.8 U5.11 U5.15 U7.22 U7.23 U7.24 U7.25 U7.26 U7.27 U7.38 U7.39 U7.40 U7.44 U7.50 U7.131 U7.132 U7.133 U7.134 U7.135 U7.136 U9.6 U9.8 U10.5 U10.6 U10.7 U10.9 U10.10 U10.11 U10.12 U10.13 U10.14

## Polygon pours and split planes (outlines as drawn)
GND on Bottom Layer "Bottom AGND Sound" (solid, remove dead copper, pour order 23): 3895.82,7627.8 3895.82,6944.18 3900,6940 3910,6950 6740,6950 6740,7620 6720,7640
GND on Bottom Layer "Bottom AGND Video" (solid, remove dead copper, pour order 22): 3940,5310 6670,5310 6670,6904.37 6350,6904.37 6350,7000 5750,7000 5760,6990 5760,6904.37 3940,6904.37
GND on Bottom Layer "Bottom AGND Sound" (solid, remove dead copper, pour order 9): 1320,5310 3908.3,5310 3912.24,7629.76 1460,7629.54 1240,7629.54 1240,7320 1320,7320
GND on Bottom Layer "Bottom Layer-GND 1" (solid, remove dead copper, pour order 8): 771,0 6760,20 6670,5280 1294.91,5280 1288.81,7630 632.02,7630
GND on Top Layer "Top AGND Sound" (solid, remove dead copper, pour order 15): 3910.65,6940.07 6670,6950 6680,7630 3890,7630 3890,7619.8 1479.8,7619.8 1480,7620 1269.04,7620 1263.27,7320 1330,7320 1330,5310 3908.85,5310
GND on Top Layer "Top AGND Video" (solid, remove dead copper, pour order 17): 3940,5310 6670,5310 6670,6914.41 6340,6913.2 6340,6970 6080,6970 6080,6912.24 3940,6904.37
GND on Top Layer "Top Layer-GND" (solid, remove dead copper, pour order 11): 770,50 6679.96,50 6670,5280 1410.39,5280 1290,5400.39 1290,7630 771,7630 771,5280 770,5279

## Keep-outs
Keep-Out Layer:
  lines w3.94: 772.97,1378.81 772.97,6536.92 ccw(c705.6,6806.38) 983.35,6806.38 983.35,6967.36 ccw(c705.6,6967.36) 772.97,7236.81 772.97,7640 6674.54,7640 6674.54,7235.33 ccw(c6598.39,6990.56) 6342.05,6990.56 6342.05,6833.17 ccw(c6598.39,6833.17) 6670.6,6587.21 6670.6,1378.81 6002.81,41.56 1440.75,41.56 772.97,1378.81 ; 1284.42,6977.4 cw(c1345.44,6977.4) 1345.44,7038.43 cw(c1345.44,6977.4) 1406.46,6977.4 cw(c1345.44,6977.4) 1345.44,6916.38 cw(c1345.44,6977.4) 1284.42,6977.4 ; 1288.35,6977.4 cw(c1345.44,6977.4) 1345.44,7034.49 cw(c1345.44,6977.4) 1402.53,6977.4 cw(c1345.44,6977.4) 1345.44,6920.31 cw(c1345.44,6977.4) 1288.35,6977.4 ; 1461.17,7189.1 cw(c1522.19,7189.1) 1522.19,7250.13 cw(c1522.19,7189.1) 1583.22,7189.1 cw(c1522.19,7189.1) 1522.19,7128.08 cw(c1522.19,7189.1) 1461.17,7189.1 ; 1465.11,7189.1 cw(c1522.19,7189.1) 1522.19,7246.19 cw(c1522.19,7189.1) 1579.28,7189.1 cw(c1522.19,7189.1) 1522.19,7132.02 cw(c1522.19,7189.1) 1465.11,7189.1 ; 1618.62,206.07 cw(c1703.93,206.07) 1703.93,291.38 cw(c1703.93,206.07) 1789.24,206.07 cw(c1703.93,206.07) 1703.93,120.76 cw(c1703.93,206.07) 1618.62,206.07 ; 1622.56,206.07 cw(c1703.93,206.07) 1703.93,287.44 cw(c1703.93,206.07) 1785.3,206.07 cw(c1703.93,206.07) 1703.93,124.7 cw(c1703.93,206.07) 1622.56,206.07 ; 1780.04,306.93 cw(c1857.86,306.93) 1857.86,384.75 cw(c1857.86,306.93) 1935.68,306.93 cw(c1857.86,306.93) 1857.86,229.11 cw(c1857.86,306.93) 1780.04,306.93 ; 1783.98,306.93 cw(c1857.86,306.93) 1857.86,380.81 cw(c1857.86,306.93) 1931.74,306.93 cw(c1857.86,306.93) 1857.86,233.05 cw(c1857.86,306.93) 1783.98,306.93 ; 1920.04,201.93 cw(c1997.86,201.93) 1997.86,279.75 cw(c1997.86,201.93) 2075.68,201.93 cw(c1997.86,201.93) 1997.86,124.11 cw(c1997.86,201.93) 1920.04,201.93 ; 1923.98,201.93 cw(c1997.86,201.93) 1997.86,275.81 cw(c1997.86,201.93) 2071.74,201.93 cw(c1997.86,201.93) 1997.86,128.05 cw(c1997.86,201.93) 1923.98,201.93 ; 1942.1,490.97 cw(c2019.92,490.97) 2019.92,568.79 cw(c2019.92,490.97) 2097.74,490.97 cw(c2019.92,490.97) 2019.92,413.15 cw(c2019.92,490.97) 1942.1,490.97 ; 1946.04,490.97 cw(c2019.92,490.97) 2019.92,564.86 cw(c2019.92,490.97) 2093.8,490.97 cw(c2019.92,490.97) 2019.92,417.09 cw(c2019.92,490.97) 1946.04,490.97 ; 3445.19,439.94 cw(c3506.22,439.94) 3506.22,500.96 cw(c3506.22,439.94) 3567.24,439.94 cw(c3506.22,439.94) 3506.22,378.91 cw(c3506.22,439.94) 3445.19,439.94 ; 3446.07,925.94 cw(c3507.09,925.94) 3507.09,986.97 cw(c3507.09,925.94) 3568.12,925.94 cw(c3507.09,925.94) 3507.09,864.92 cw(c3507.09,925.94) 3446.07,925.94 ; 3446.17,7184.1 cw(c3507.19,7184.1) 3507.19,7245.13 cw(c3507.19,7184.1) 3568.22,7184.1 cw(c3507.19,7184.1) 3507.19,7123.08 cw(c3507.19,7184.1) 3446.17,7184.1 ; 3449.13,439.94 cw(c3506.22,439.94) 3506.22,497.02 cw(c3506.22,439.94) 3563.31,439.94 cw(c3506.22,439.94) 3506.22,382.85 cw(c3506.22,439.94) 3449.13,439.94 ; 3450.01,925.94 cw(c3507.09,925.94) 3507.09,983.03 cw(c3507.09,925.94) 3564.18,925.94 cw(c3507.09,925.94) 3507.09,868.86 cw(c3507.09,925.94) 3450.01,925.94 ; 3450.11,7184.1 cw(c3507.19,7184.1) 3507.19,7241.19 cw(c3507.19,7184.1) 3564.28,7184.1 cw(c3507.19,7184.1) 3507.19,7127.02 cw(c3507.19,7184.1) 3450.11,7184.1 ; 3734.42,6747.4 cw(c3795.44,6747.4) 3795.44,6808.43 cw(c3795.44,6747.4) 3856.46,6747.4 cw(c3795.44,6747.4) 3795.44,6686.38 cw(c3795.44,6747.4) 3734.42,6747.4 ; 3738.35,6747.4 cw(c3795.44,6747.4) 3795.44,6804.49 cw(c3795.44,6747.4) 3852.53,6747.4 cw(c3795.44,6747.4) 3795.44,6690.31 cw(c3795.44,6747.4) 3738.35,6747.4 ; 4904.11,492.86 cw(c4981.93,492.86) 4981.93,570.68 cw(c4981.93,492.86) 5059.75,492.86 cw(c4981.93,492.86) 4981.93,415.04 cw(c4981.93,492.86) 4904.11,492.86 ; 4907.18,204.15 ccw(c4985,204.15) 4985,126.33 ccw(c4985,204.15) 5062.82,204.15 ccw(c4985,204.15) 4985,281.97 ccw(c4985,204.15) 4907.18,204.15 ; 4908.05,492.86 cw(c4981.93,492.86) 4981.93,566.74 cw(c4981.93,492.86) 5055.81,492.86 cw(c4981.93,492.86) 4981.93,418.98 cw(c4981.93,492.86) 4908.05,492.86 ; 4911.12,204.15 ccw(c4985,204.15) 4985,130.27 ccw(c4985,204.15) 5058.88,204.15 ccw(c4985,204.15) 4985,278.03 ccw(c4985,204.15) 4911.12,204.15 ; 5062.38,290.61 cw(c5140.2,290.61) 5140.2,368.43 cw(c5140.2,290.61) 5218.02,290.61 cw(c5140.2,290.61) 5140.2,212.78 cw(c5140.2,290.61) 5062.38,290.61 ; 5066.32,290.61 ccw(c5140.2,290.61) 5140.2,216.72 ccw(c5140.2,290.61) 5214.08,290.61 ccw(c5140.2,290.61) 5140.2,364.49 ccw(c5140.2,290.61) 5066.32,290.61 ; 6049.87,6427.19 cw(c6110.9,6427.19) 6110.9,6488.22 cw(c6110.9,6427.19) 6171.92,6427.19 cw(c6110.9,6427.19) 6110.9,6366.17 cw(c6110.9,6427.19) 6049.87,6427.19 ; 6053.81,6427.19 cw(c6110.9,6427.19) 6110.9,6484.28 cw(c6110.9,6427.19) 6167.98,6427.19 cw(c6110.9,6427.19) 6110.9,6370.11 cw(c6110.9,6427.19) 6053.81,6427.19

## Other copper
Top Layer:
  region: 8680,0
  region: 8680,0
  region: 8680,0
  region: 8680,0
  region: 8680,0
  region: 8680,0
  region: 8680,0
  region: 8680,0
  region: 7697,1765.63
  region: 7697,1765.63
  region: 7697,1765.63
  region: 7697,1765.63
  region: 7697,1765.63
  region: 7697,1765.63
  region: 7697,1765.63
  region: 7697,1765.63
  region: 7580,1720
  region: 7580,1720
  region: 7580,1720
  region: 7580,1720
  region: 7580,1720
  region: 7580,1720
  region: 7580,1720
  region: 7580,1720

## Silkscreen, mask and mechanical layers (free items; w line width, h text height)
Top Overlay:
  drawing of 45 lines, arcs and shapes, not listed
  text "STEREO / MONO" at 2850.11,5560 h45
  text "REGION" at 6260,4420 h60
  text "USA" at 6172.11,4275.87 h42
  text "EUROPE" at 6182.11,4035.87 h42
  text "JAPAN" at 6180,3950 h42
  text "youtube.com/hotpixel" at 1066.88,3692.24 h110
  text "VIDEO MODE" at 5970,3420 h60
  text "801" at 2180,3250 h45
  text "801-A1" at 1470,3240 h45
  text "NTSC" at 6230,3240 h42
  text "PAL" at 6230,3030 h42
  text "801" at 2790,1900 h60
  text "801-A1" at 2110,1880 h60
  text "EHODRIVE" at 5050,1670 h120
  text "The  Eight  Hundred  One  remake" at 5045,1530 h135
  text "ver 1.2" at 6220,1430.66 h110
  text "14.318 MHz" at 3210,1050 h45
  text "17.734 MHz" at 4140,1040 h45
  text "RESET" at 5060,860 h60
  text "POWER" at 1800,800 h60
Bottom Overlay:
  text "REGION" at 6582,4430 h60
  text "USA" at 6364.08,4285.87 h42
  text "EUROPE" at 6490.03,4045.87 h42
  text "JAPAN" at 6448.05,3960 h42
  text "VIDEO MODE" at 6614.48,3398.12 h60
  text "NTSC" at 6354.48,3218.12 h42
  text "PAL" at 6354.48,3008.12 h42
Mechanical 1:
  circle w0.5: c3507.09,925.94 r59.06
  circle w0.5: c1948.73,5118.73 r29.4
  circle w0.5: c2048.73,5118.73 r29.4
  circle w0.5: c2148.73,5118.73 r29.4
  circle w0.5: c2248.73,5118.73 r29.4
  circle w0.5: c2348.73,5118.73 r29.4
  circle w0.5: c2448.73,5118.73 r29.4
  circle w0.5: c2548.73,5118.73 r29.4
  circle w0.5: c2648.73,5118.73 r29.4
  circle w0.5: c2748.73,5118.73 r29.4
  circle w0.5: c2848.73,5118.73 r29.4
  circle w0.5: c2948.73,5118.73 r29.4
  circle w0.5: c3048.73,5118.73 r29.4
  circle w0.5: c3148.73,5118.73 r29.4
  circle w0.5: c3248.73,5118.73 r29.4
  circle w0.5: c3348.73,5118.73 r29.4
  circle w0.5: c3448.73,5118.73 r29.4
  circle w0.5: c3548.73,5118.73 r29.4
  circle w0.5: c3648.73,5118.73 r29.4
  circle w0.5: c3748.73,5118.73 r29.4
  circle w0.5: c3848.73,5118.73 r29.4
  circle w0.5: c3948.73,5118.73 r29.4
  circle w0.5: c4048.73,5118.73 r29.4
  circle w0.5: c4148.73,5118.73 r29.4
  circle w0.5: c4248.73,5118.73 r29.4
  circle w0.5: c4348.73,5118.73 r29.4
  circle w0.5: c4448.73,5118.73 r29.4
  circle w0.5: c4548.73,5118.73 r29.4
  circle w0.5: c4648.73,5118.73 r29.4
  circle w0.5: c4748.73,5118.73 r29.4
  circle w0.5: c4848.73,5118.73 r29.4
  circle w0.5: c4948.73,5118.73 r29.4
  circle w0.5: c5048.73,5118.73 r29.4
  circle w0.5: c2048.73,4918.73 r29.4
  circle w0.5: c1948.73,4918.73 r29.4
  circle w0.5: c2148.73,4918.73 r29.4
  circle w0.5: c2248.73,4918.73 r29.4
  circle w0.5: c2348.73,4918.73 r29.4
  circle w0.5: c2448.73,4918.73 r29.4
  circle w0.5: c2548.73,4918.73 r29.4
  circle w0.5: c2648.73,4918.73 r29.4
  circle w0.5: c5048.73,4918.73 r29.4
  circle w0.5: c4948.73,4918.73 r29.4
  circle w0.5: c4848.73,4918.73 r29.4
  circle w0.5: c4748.73,4918.73 r29.4
  circle w0.5: c4648.73,4918.73 r29.4
  circle w0.5: c4548.73,4918.73 r29.4
  circle w0.5: c4448.73,4918.73 r29.4
  circle w0.5: c4348.73,4918.73 r29.4
  circle w0.5: c4248.73,4918.73 r29.4
  circle w0.5: c4148.73,4918.73 r29.4
  circle w0.5: c4048.73,4918.73 r29.4
  circle w0.5: c3948.73,4918.73 r29.4
  circle w0.5: c3848.73,4918.73 r29.4
  circle w0.5: c3748.73,4918.73 r29.4
  circle w0.5: c3648.73,4918.73 r29.4
  circle w0.5: c3548.73,4918.73 r29.4
  circle w0.5: c3448.73,4918.73 r29.4
  circle w0.5: c3348.73,4918.73 r29.4
  circle w0.5: c3248.73,4918.73 r29.4
  circle w0.5: c3148.73,4918.73 r29.4
  circle w0.5: c3048.73,4918.73 r29.4
  circle w0.5: c2948.73,4918.73 r29.4
  circle w0.5: c2848.73,4918.73 r29.4
  circle w0.5: c2748.73,4918.73 r29.4
  circle w0.5: c1611.97,5017.22 r78.23
  circle w0.5: c5384.67,5017.22 r72
  circle w0.5: c3506.22,439.94 r59.06
  circle w0.5: c2662.43,335.26 r25.64
  circle w0.5: c2771.48,335.26 r25.64
  circle w0.5: c2880.54,335.26 r25.64
  circle w0.5: c2989.59,335.26 r25.64
  circle w0.5: c3098.65,335.26 r25.64
  circle w0.5: c3916.24,335.26 r25.64
  circle w0.5: c4025.3,335.26 r25.64
  circle w0.5: c4134.35,335.26 r25.64
  circle w0.5: c4243.41,335.26 r25.64
  circle w0.5: c4352.46,335.26 r25.64
  lines w0.5: 1557.31,948.98 1557.31,1242.19 2393.19,1242.19 2393.19,948.98 1557.31,948.98 ; 5002.5,923.76 5002.5,1312.05 5393.21,1312.05 5393.21,923.76 5002.5,923.76
Mechanical 15:
  lines w0.5: 979.41,6806.38 979.41,6967.36 ; 6345.99,6833.17 6345.99,6990.56
  lines w3.94: 6676.15,7232.75 ccw(c6598.39,6990.56) 6344.02,6990.56 6344.02,6833.17 ccw(c6598.39,6833.17) 6672.57,6589.85 6672.57,1378.35 6004.03,39.59 1439.54,39.59 771,1378.35 771,6538.46 ccw(c705.6,6806.38) 981.38,6806.38 981.38,6967.36 ccw(c705.6,6967.36) 771,7235.27 771,7640 6676.51,7640 6676.51,7232.75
